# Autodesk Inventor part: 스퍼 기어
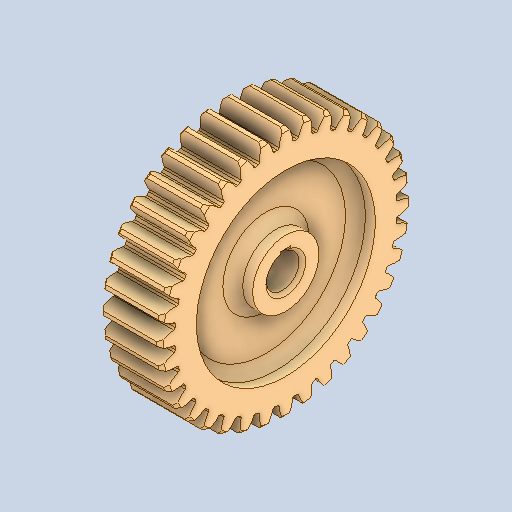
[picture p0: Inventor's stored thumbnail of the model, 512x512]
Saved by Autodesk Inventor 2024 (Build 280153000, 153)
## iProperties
Created: 2025-10
Part Number: 스퍼 기어
Material: 강철, 합금
Document SubType Name: Modeling
Designer: EDU03
Density: 7.73 g/cm^3
Appearance: 기본값
Author: jhkim
Sending System: Autodesk Inventor 2026
Preprocessor: ST-DEVELOPER v20.1
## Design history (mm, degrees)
feature "솔리드1"
node "솔리드2"
